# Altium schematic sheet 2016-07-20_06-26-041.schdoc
size 212 x 129 mm; SheetNumber: 1; SheetTotal: 1
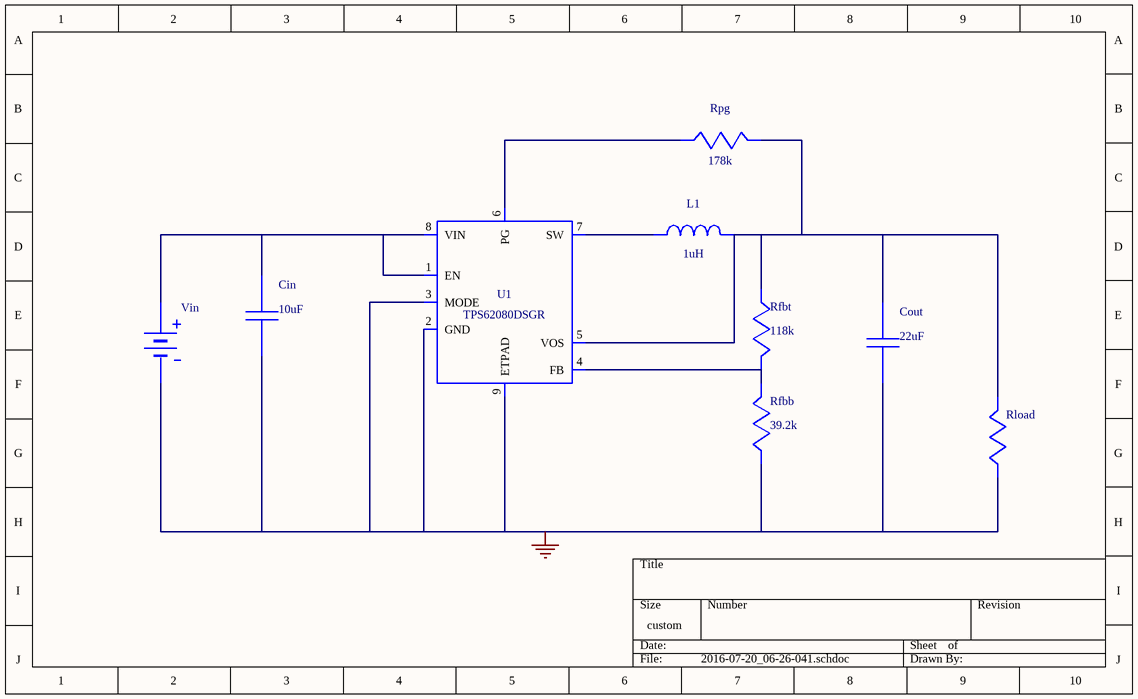
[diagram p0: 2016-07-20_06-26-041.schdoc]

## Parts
Cin  value 10uF  (hidden comment: JMK212BJ106KD-T)
Cout  value 22uF  (hidden comment: JMK212BJ226KG-T)
L1  value 1uH  (hidden comment: PFL3215-102MEB)
Rfbb  value 39.2k  (hidden comment: CRCW040239K2FKED)
Rfbt  value 118k  (hidden comment: CRCW0402118KFKED)
Rload  WB_LOAD_RESISTOR  (value not drawn)
Rpg  value 178k  (hidden comment: CRCW0402178KFKED)
U1  TPS62080DSGR
Vin  WB_BATTERY  (value not drawn)

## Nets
0: Cin.2 Cout.2 Rfbb.2 Rload.2 U1.2(GND) U1.3(MODE) U1.9(ETPAD) Vin.2(-)
NetCin_1: Cin.1 U1.1(EN) U1.8(VIN) Vin.1(+)
NetCout_1: Cout.1 L1.2 Rfbt.2 Rload.1 Rpg.1 U1.5(VOS)
NetL1_1: L1.1 U1.7(SW)
NetRfbb_1: Rfbb.1 Rfbt.1 U1.4(FB)
NetRpg_2: Rpg.2 U1.6(PG)

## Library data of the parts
Cin = JMK212BJ106KD-T: Manufacturer Name: Taiyo Yuden
Cout = JMK212BJ226KG-T: Manufacturer Name: Taiyo Yuden
L1 = PFL3215-102MEB: Unknown; Manufacturer Name: Coilcraft
Rfbb = CRCW040239K2FKED: Manufacturer Name: Vishay-Dale
Rfbt = CRCW0402118KFKED: Manufacturer Name: Vishay-Dale
Rpg = CRCW0402178KFKED: Manufacturer Name: Vishay-Dale
U1 = TPS62080DSGR: Manufacturer Name: Texas Instruments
